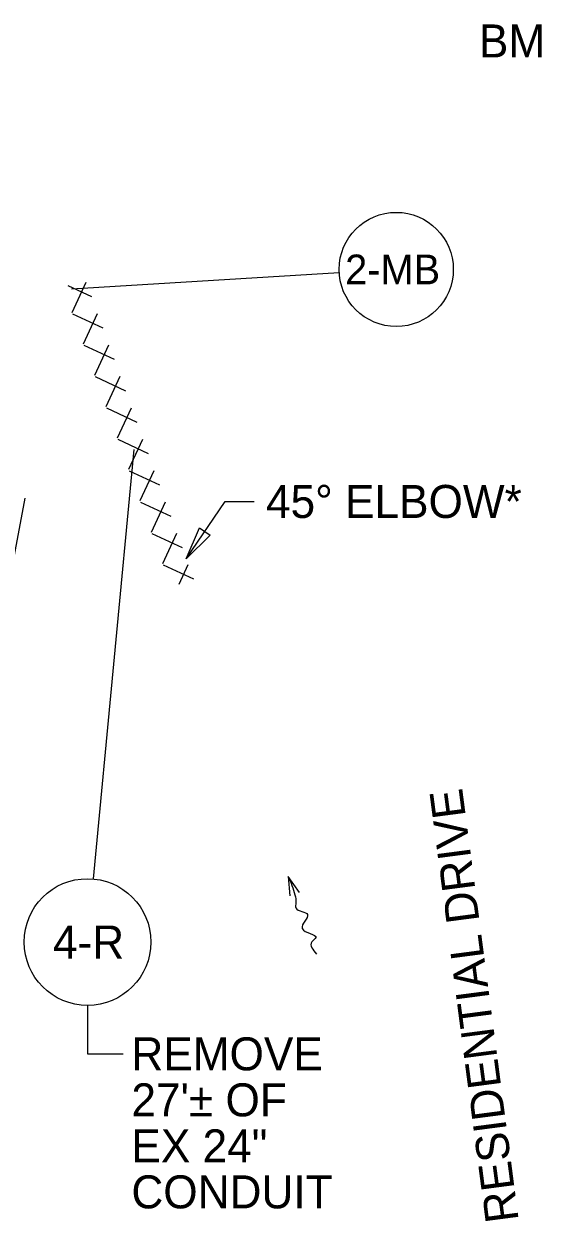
# Model space of a CAD drawing. Extents: x 0 to 3369, y -440 to 440.
# Drawn here: x 542.9 to 586.9, y 209.7 to 311.2 of the extents above; entities that cross this region are included whole.
import ezdxf

# ---------------------------------------------------------------- set-up
doc = ezdxf.new("R2010")
doc.units = 0
for name, color, linetype in [('_CIVIL_CONSTRUCTION', 7, 'Continuous'), ('MT_P_PCB', 7, 'Continuous'), ('MT_P_Work_Area', 7, 'Continuous'), ('PV_P_EOP', 7, 'Continuous')]:
    doc.layers.add(name, color=color, linetype=linetype)

msp = doc.modelspace()

# ---------------------------------------------------------------- linework, layer by layer
at = {"layer": '_CIVIL_CONSTRUCTION'}
msp.add_lwpolyline([(557.72, 268.43), (558.64, 267.8), (556.61, 265.8)], close=True, dxfattribs=at)
at = {"layer": 'MT_P_PCB'}
for p, q in [((546.93, 286.7), (548.13, 289.26)), ((546.58, 288.98), (548.57, 288.04)), ((546.97, 286.58), (549.53, 285.38)), ((547.89, 284.04), (549.09, 286.6)), ((547.93, 283.92), (550.49, 282.72)), ((548.85, 281.38), (550.05, 283.94)), ((548.89, 281.26), (551.45, 280.06)), ((549.81, 278.72), (551.01, 281.28)), ((549.85, 278.6), (552.41, 277.4)), ((550.77, 276.06), (551.97, 278.62)), ((550.81, 275.94), (553.37, 274.74)), ((551.73, 273.4), (552.93, 275.96)), ((551.77, 273.28), (554.33, 272.08)), ((552.69, 270.74), (553.9, 273.3)), ((552.74, 270.62), (555.3, 269.42)), ((553.66, 268.08), (554.86, 270.64)), ((553.7, 267.96), (556.26, 266.76)), ((554.62, 265.42), (555.82, 267.98)), ((554.66, 265.3), (557.22, 264.1)), ((556.01, 263.67), (556.78, 265.32))]:
    msp.add_line(p, q, dxfattribs=at)
at = {"layer": 'MT_P_Work_Area'}
for p, q in [((566.2, 237.52), (565.26, 238.88)), ((565.26, 238.88), (565.4, 237.23))]:
    msp.add_line(p, q, dxfattribs=at)
msp.add_spline([(565.26, 238.88), (565.82, 237.32), (565.9, 236.65), (565.91, 236.21), (566.89, 235.66), (566.44, 234.47), (567.6, 233.69), (567.25, 233.33), (567.64, 232.3)], degree=3, dxfattribs=at)
at = {"layer": 'PV_P_EOP'}
for p, q in [((569.58, 290.05), (546.87, 288.66)), ((548.75, 238.67), (552.19, 275.08)), ((538.44, 246.95), (542.94, 270.94)), ((556.61, 265.8), (559.92, 270.67)), ((559.92, 270.67), (562.38, 270.67)), ((548.24, 227.95), (548.24, 223.84)), ((548.24, 223.84), (551.26, 223.84))]:
    msp.add_line(p, q, dxfattribs=at)
for centre, radius in [((574.41, 290.34), 4.84), ((548.24, 233.32), 5.37)]:
    msp.add_circle(centre, radius, dxfattribs=at)

# ---------------------------------------------------------------- texts
at = {"layer": 'MT_P_PCB'}
msp.add_text('RESIDENTIAL DRIVE', height=2.8, rotation=97.4647, dxfattribs=at).set_placement((584.8, 209.72))
at = {"layer": 'PV_P_EOP'}
for s, height, p in [('BM 3', 2.8, (581.42, 308.31)), ('2-MB', 2.52, (570.08, 289.08)), ('45° ELBOW*', 2.8, (563.37, 269.27)), ('4-R', 2.8, (545.31, 231.92)), ('REMOVE', 2.8, (551.96, 222.44)), ("27'± OF", 2.8, (551.96, 218.54)), ('EX 24"', 2.8, (551.96, 214.64)), ('CONDUIT', 2.8, (551.96, 210.74))]:
    msp.add_text(s, height=height, dxfattribs=at).set_placement(p)

doc.saveas('drawing.dxf')
